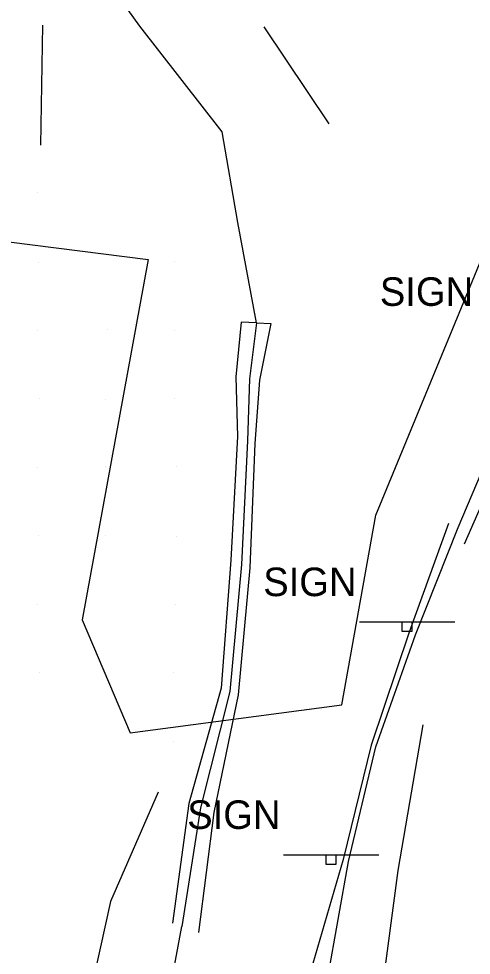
# Model space of a CAD drawing. Extents: x 1602514 to 1609837, y 863887 to 871157.
# Drawn here: x 1604773.2 to 1604872.3, y 867056.2 to 867261.2 of the extents above; entities that cross this region are included whole.
import ezdxf

# ---------------------------------------------------------------- set-up
doc = ezdxf.new("R2010")
doc.units = 0
for name, color, linetype in [('Roadway-Signs', 7, 'Continuous'), ('Survey-Ditches', 7, 'Continuous'), ('Survey-Edge of pavement', 7, 'Continuous'), ('Survey-Flow line', 7, 'Continuous'), ('Survey-Ridge Lines', 7, 'Continuous'), ('Survey-Safety', 7, 'Continuous'), ('Survey-Shoulders', 7, 'Continuous'), ('Survey-Spot dirt', 7, 'Continuous'), ('Survey-Vegetation trees', 7, 'Continuous')]:
    doc.layers.add(name, color=color, linetype=linetype)

msp = doc.modelspace()

# ---------------------------------------------------------------- linework, layer by layer
at = {"layer": 'Roadway-Signs'}
for p, q in [((1604847.83, 867129.15), (1604868.73, 867129.15)), ((1604847.83, 867129.15), (1604868.73, 867129.15)), ((1604857.18, 867127.05), (1604857.18, 867129.15)), ((1604857.18, 867127.05), (1604857.18, 867129.15)), ((1604858.23, 867129.15), (1604858.23, 867129.15)), ((1604858.23, 867129.15), (1604858.23, 867129.15)), ((1604859.28, 867129.15), (1604859.28, 867127.05)), ((1604859.28, 867129.15), (1604859.28, 867127.05)), ((1604859.28, 867127.05), (1604857.18, 867127.05)), ((1604859.28, 867127.05), (1604857.18, 867127.05)), ((1604831.18, 867078.19), (1604852.08, 867078.19)), ((1604831.18, 867078.19), (1604852.08, 867078.19)), ((1604840.53, 867076.09), (1604840.53, 867078.19)), ((1604840.53, 867076.09), (1604840.53, 867078.19)), ((1604841.58, 867078.19), (1604841.58, 867078.19)), ((1604841.58, 867078.19), (1604841.58, 867078.19)), ((1604842.63, 867078.19), (1604842.63, 867076.09)), ((1604842.63, 867078.19), (1604842.63, 867076.09)), ((1604842.63, 867076.09), (1604840.53, 867076.09)), ((1604842.63, 867076.09), (1604840.53, 867076.09))]:
    msp.add_line(p, q, dxfattribs=at)
at = {"layer": 'Survey-Ditches'}
for points in [[(1604825.24, 867194.65), (1604821.94, 867194.79), (1604820.73, 867182.82), (1604821.1, 867169.75), (1604819.65, 867142.7), (1604817.56, 867114.65), (1604810.47, 867089.43), (1604806.85, 867063.21)], [(1604825.24, 867194.65), (1604821.94, 867194.79), (1604820.73, 867182.82), (1604821.1, 867169.75), (1604819.65, 867142.7), (1604817.56, 867114.65), (1604810.47, 867089.43), (1604806.85, 867063.21)], [(1604825.24, 867194.65), (1604823.76, 867182.37), (1604823.31, 867168.84), (1604822.02, 867141.74), (1604819.42, 867113.95), (1604813.02, 867088.5), (1604808.94, 867062.48)], [(1604825.24, 867194.65), (1604823.76, 867182.37), (1604823.31, 867168.84), (1604822.02, 867141.74), (1604819.42, 867113.95), (1604813.02, 867088.5), (1604808.94, 867062.48)], [(1604825.24, 867194.65), (1604828.39, 867194.52), (1604825.91, 867182.06), (1604824.9, 867168.19), (1604823.84, 867141), (1604821.29, 867113.24), (1604815.94, 867087.44), (1604812.56, 867061.21)], [(1604825.24, 867194.65), (1604828.39, 867194.52), (1604825.91, 867182.06), (1604824.9, 867168.19), (1604823.84, 867141), (1604821.29, 867113.24), (1604815.94, 867087.44), (1604812.56, 867061.21)]]:
    msp.add_lwpolyline(points, dxfattribs=at)
at = {"layer": 'Survey-Edge of pavement'}
msp.add_lwpolyline([(1604861.7, 867106.64), (1604856.22, 867074.72), (1604850.49, 867031.3)], dxfattribs=at)
msp.add_lwpolyline([(1604861.7, 867106.64), (1604856.22, 867074.72), (1604850.49, 867031.3)], dxfattribs=at)
at = {"layer": 'Survey-Flow line'}
for points in [[(1604825.24, 867194.65), (1604821.17, 867216.57), (1604817.74, 867236.45), (1604799.75, 867259.61), (1604775.29, 867293.59), (1604776.33, 867315.88), (1604792.23, 867342.57), (1604806.9, 867375.02), (1604822.2, 867411.61), (1604827.76, 867442.51), (1604835.8, 867478.97), (1604831.81, 867504.07), (1604821.12, 867538.37), (1604811.33, 867580.91), (1604816.48, 867615.89), (1604831.53, 867651.16)], [(1604825.24, 867194.65), (1604821.17, 867216.57), (1604817.74, 867236.45), (1604799.75, 867259.61), (1604775.29, 867293.59), (1604776.33, 867315.88), (1604792.23, 867342.57), (1604806.9, 867375.02), (1604822.2, 867411.61), (1604827.76, 867442.51), (1604835.8, 867478.97), (1604831.81, 867504.07), (1604821.12, 867538.37), (1604811.33, 867580.91), (1604816.48, 867615.89), (1604831.53, 867651.16)], [(1604783.74, 867018.15), (1604798.93, 867030.07), (1604805.46, 867044.14), (1604808.94, 867062.48)], [(1604783.74, 867018.15), (1604798.93, 867030.07), (1604805.46, 867044.14), (1604808.94, 867062.48)]]:
    msp.add_lwpolyline(points, dxfattribs=at)
at = {"layer": 'Survey-Ridge Lines'}
for p, q in [((1604778.03, 867233.51), (1604778.5, 867259.78)), ((1604778.03, 867233.51), (1604778.5, 867259.78)), ((1604826.88, 867259.4), (1604841.08, 867238.17)), ((1604826.88, 867259.4), (1604841.08, 867238.17))]:
    msp.add_line(p, q, dxfattribs=at)
for points in [[(1604867.32, 867150.71), (1604858.73, 867126.89), (1604850.4, 867102.2), (1604844.23, 867077.16), (1604837.12, 867052.62), (1604832.39, 867016.31)], [(1604867.32, 867150.71), (1604858.73, 867126.89), (1604850.4, 867102.2), (1604844.23, 867077.16), (1604837.12, 867052.62), (1604832.39, 867016.31)], [(1604803.71, 867091.89), (1604793.31, 867067.95), (1604782.89, 867020.67)], [(1604803.71, 867091.89), (1604793.31, 867067.95), (1604782.89, 867020.67)]]:
    msp.add_lwpolyline(points, dxfattribs=at)
at = {"layer": 'Survey-Safety'}
for points in [[(1604869.46, 867149.82), (1604883.76, 867183.53), (1604909.88, 867239.67), (1604935.96, 867296.39), (1604961.66, 867354.13), (1604979.87, 867396.58), (1605000.58, 867444.11)], [(1604869.46, 867149.82), (1604883.76, 867183.53), (1604909.88, 867239.67), (1604935.96, 867296.39), (1604961.66, 867354.13), (1604979.87, 867396.58), (1605000.58, 867444.11)], [(1604837.1, 867025.75), (1604840.9, 867051.3), (1604845.45, 867076.72), (1604851.39, 867101.82), (1604860.1, 867126.34), (1604869.46, 867149.82)], [(1604837.1, 867025.75), (1604840.9, 867051.3), (1604845.45, 867076.72), (1604851.39, 867101.82), (1604860.1, 867126.34), (1604869.46, 867149.82)]]:
    msp.add_lwpolyline(points, dxfattribs=at)
at = {"layer": 'Survey-Shoulders'}
msp.add_lwpolyline([(1604973.2, 867376.11), (1604963.74, 867353.22), (1604953.68, 867330.37), (1604943.99, 867307.34), (1604933.6, 867284.64), (1604923.3, 867261.89), (1604912.68, 867239.29), (1604902.24, 867216.61), (1604891.85, 867193.71), (1604881.64, 867170.93), (1604870.75, 867146.16)], dxfattribs=at)
msp.add_lwpolyline([(1604973.2, 867376.11), (1604963.74, 867353.22), (1604953.68, 867330.37), (1604943.99, 867307.34), (1604933.6, 867284.64), (1604923.3, 867261.89), (1604912.68, 867239.29), (1604902.24, 867216.61), (1604891.85, 867193.71), (1604881.64, 867170.93), (1604870.75, 867146.16)], dxfattribs=at)
at = {"layer": 'Survey-Spot dirt'}
for p, q in [((1604777.32, 867223.23), (1604777.32, 867223.23)), ((1604777.32, 867223.23), (1604777.32, 867223.23)), ((1604777.44, 867207.86), (1604777.44, 867207.86)), ((1604777.44, 867207.86), (1604777.44, 867207.86)), ((1604807.38, 867208.1), (1604807.38, 867208.1)), ((1604807.38, 867208.1), (1604807.38, 867208.1)), ((1604777.34, 867192.89), (1604777.34, 867192.89)), ((1604777.34, 867192.89), (1604777.34, 867192.89)), ((1604792.58, 867193.21), (1604792.58, 867193.21)), ((1604792.58, 867193.21), (1604792.58, 867193.21)), ((1604807.4, 867192.99), (1604807.4, 867192.99)), ((1604807.4, 867192.99), (1604807.4, 867192.99)), ((1604777.65, 867178.02), (1604777.65, 867178.02)), ((1604777.65, 867178.02), (1604777.65, 867178.02)), ((1604792.17, 867177.95), (1604792.17, 867177.95)), ((1604792.17, 867177.95), (1604792.17, 867177.95)), ((1604807.31, 867178.15), (1604807.31, 867178.15)), ((1604807.31, 867178.15), (1604807.31, 867178.15)), ((1604807.65, 867163.25), (1604807.65, 867163.25)), ((1604807.65, 867163.25), (1604807.65, 867163.25)), ((1604777.28, 867163.01), (1604777.28, 867163.01)), ((1604777.28, 867163.01), (1604777.28, 867163.01)), ((1604792.31, 867163.11), (1604792.31, 867163.11)), ((1604792.31, 867163.11), (1604792.31, 867163.11)), ((1604777.45, 867148.11), (1604777.45, 867148.11)), ((1604777.45, 867148.11), (1604777.45, 867148.11)), ((1604792.29, 867147.99), (1604792.29, 867147.99)), ((1604792.29, 867147.99), (1604792.29, 867147.99)), ((1604807.76, 867147.95), (1604807.76, 867147.95)), ((1604807.76, 867147.95), (1604807.76, 867147.95)), ((1604777.35, 867133.02), (1604777.35, 867133.02)), ((1604777.35, 867133.02), (1604777.35, 867133.02)), ((1604807.52, 867132.94), (1604807.52, 867132.94)), ((1604807.52, 867132.94), (1604807.52, 867132.94)), ((1604777.75, 867118.17), (1604777.75, 867118.17)), ((1604777.75, 867118.17), (1604777.75, 867118.17)), ((1604807.12, 867118.15), (1604807.12, 867118.15)), ((1604807.12, 867118.15), (1604807.12, 867118.15)), ((1604792.31, 867117.81), (1604792.31, 867117.81)), ((1604792.31, 867117.81), (1604792.31, 867117.81)), ((1604807.18, 867103.07), (1604807.18, 867103.07)), ((1604807.18, 867103.07), (1604807.18, 867103.07))]:
    msp.add_line(p, q, dxfattribs=at)
at = {"layer": 'Survey-Vegetation trees'}
msp.add_lwpolyline([(1604694.29, 867241.17), (1604761.2, 867213.64), (1604801.54, 867208.51), (1604801.54, 867208.51), (1604787.08, 867129.65), (1604797.58, 867104.92), (1604843.97, 867110.99), (1604851.44, 867152.52), (1604874.98, 867209.67), (1604894.34, 867232.07), (1604886.88, 867265.43), (1604897.6, 867280.59), (1604896.44, 867305.56), (1604898.3, 867346.15), (1604914.16, 867376.71), (1604910.89, 867413.34), (1604878.95, 867460), (1604876.85, 867493.59)], dxfattribs=at)
msp.add_lwpolyline([(1604694.29, 867241.17), (1604761.2, 867213.64), (1604801.54, 867208.51), (1604801.54, 867208.51), (1604787.08, 867129.65), (1604797.58, 867104.92), (1604843.97, 867110.99), (1604851.44, 867152.52), (1604874.98, 867209.67), (1604894.34, 867232.07), (1604886.88, 867265.43), (1604897.6, 867280.59), (1604896.44, 867305.56), (1604898.3, 867346.15), (1604914.16, 867376.71), (1604910.89, 867413.34), (1604878.95, 867460), (1604876.85, 867493.59)], dxfattribs=at)

# ---------------------------------------------------------------- texts
at = {"layer": 'Roadway-Signs'}
for p in [(1604852.29, 867198.35), (1604852.29, 867198.35), (1604826.75, 867134.81), (1604826.75, 867134.81), (1604810.1, 867083.85), (1604810.1, 867083.85)]:
    msp.add_text('SIGN', height=6.25, dxfattribs=at).set_placement(p)

doc.saveas('drawing.dxf')
